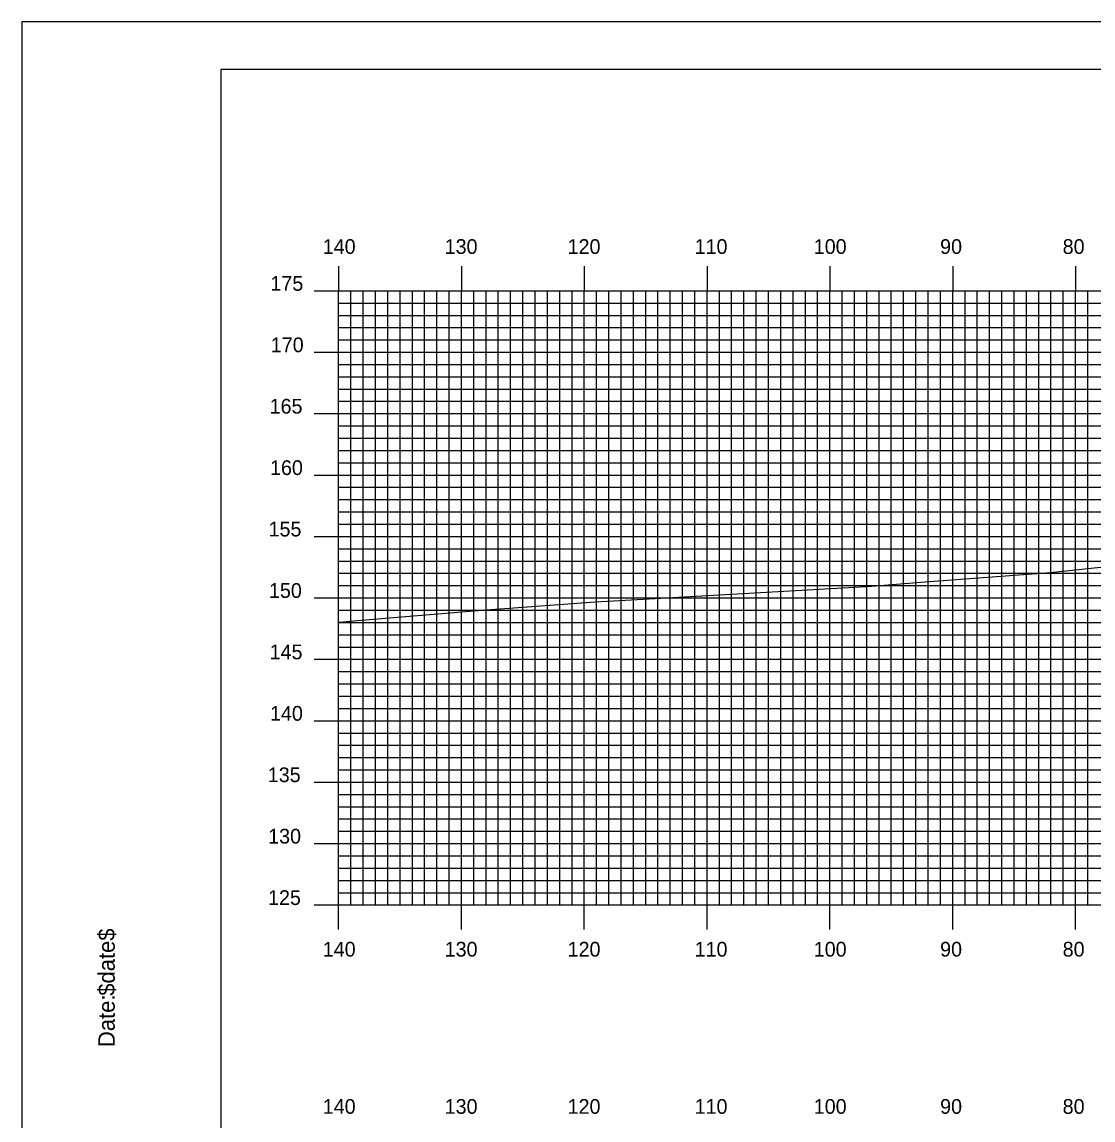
# Model space of a CAD drawing. Extents: x 1783041 to 1783384, y 442591 to 442811.
# Drawn here: x 1783040.7 to 1783127.9, y 442721.2 to 442810.5 of the extents above; entities that cross this region are included whole.
import ezdxf

# ---------------------------------------------------------------- set-up
doc = ezdxf.new("R2010")
doc.units = 0
for name, color, linetype in [('BORDER', 7, 'Continuous'), ('H_V ANNOTATION', 7, 'Continuous'), ('MAJOR', 7, 'Continuous'), ('MINOR', 7, 'Continuous'), ('PLOT BOUNDARY', 7, 'Continuous'), ('S_Roadway_Centerline', 7, 'Continuous')]:
    doc.layers.add(name, color=color, linetype=linetype)

msp = doc.modelspace()

# ---------------------------------------------------------------- linework, layer by layer
at = {"layer": 'BORDER'}
msp.add_lwpolyline([(1783056.86, 442596.665), (1783376.86, 442596.665), (1783376.86, 442806.665), (1783056.86, 442806.665)], close=True, dxfattribs=at)
at = {"layer": 'MAJOR'}
for p, q in [((1783066.46, 442790.669), (1783066.46, 442788.665)), ((1783076.46, 442790.669), (1783076.46, 442788.665)), ((1783086.46, 442790.669), (1783086.46, 442788.665)), ((1783096.46, 442790.669), (1783096.46, 442788.665)), ((1783106.46, 442790.669), (1783106.46, 442788.665)), ((1783116.46, 442790.669), (1783116.46, 442788.665)), ((1783126.46, 442790.669), (1783126.46, 442788.665)), ((1783064.456, 442788.665), (1783066.46, 442788.665)), ((1783066.46, 442788.665), (1783346.46, 442788.665)), ((1783066.46, 442738.665), (1783066.46, 442788.665)), ((1783066.46, 442738.665), (1783066.46, 442788.665)), ((1783066.46, 442788.665), (1783346.46, 442788.665)), ((1783076.46, 442738.665), (1783076.46, 442788.665)), ((1783086.46, 442738.665), (1783086.46, 442788.665)), ((1783096.46, 442738.665), (1783096.46, 442788.665)), ((1783106.46, 442738.665), (1783106.46, 442788.665)), ((1783116.46, 442738.665), (1783116.46, 442788.665)), ((1783126.46, 442738.665), (1783126.46, 442788.665)), ((1783064.456, 442783.665), (1783066.46, 442783.665)), ((1783066.46, 442783.665), (1783346.46, 442783.665)), ((1783064.456, 442778.665), (1783066.46, 442778.665)), ((1783066.46, 442778.665), (1783346.46, 442778.665)), ((1783064.456, 442773.665), (1783066.46, 442773.665)), ((1783066.46, 442773.665), (1783346.46, 442773.665)), ((1783064.456, 442768.665), (1783066.46, 442768.665)), ((1783066.46, 442768.665), (1783346.46, 442768.665)), ((1783064.456, 442763.665), (1783066.46, 442763.665)), ((1783066.46, 442763.665), (1783346.46, 442763.665)), ((1783064.456, 442758.665), (1783066.46, 442758.665)), ((1783066.46, 442758.665), (1783346.46, 442758.665)), ((1783064.456, 442753.665), (1783066.46, 442753.665)), ((1783066.46, 442753.665), (1783346.46, 442753.665)), ((1783064.456, 442748.665), (1783066.46, 442748.665)), ((1783066.46, 442748.665), (1783346.46, 442748.665)), ((1783064.456, 442743.665), (1783066.46, 442743.665)), ((1783066.46, 442743.665), (1783346.46, 442743.665)), ((1783064.456, 442738.665), (1783066.46, 442738.665)), ((1783066.46, 442738.665), (1783346.46, 442738.665)), ((1783066.46, 442738.665), (1783346.46, 442738.665)), ((1783066.46, 442736.661), (1783066.46, 442738.665)), ((1783076.46, 442736.661), (1783076.46, 442738.665)), ((1783086.46, 442736.661), (1783086.46, 442738.665)), ((1783096.46, 442736.661), (1783096.46, 442738.665)), ((1783106.46, 442736.661), (1783106.46, 442738.665)), ((1783116.46, 442736.661), (1783116.46, 442738.665)), ((1783126.46, 442736.661), (1783126.46, 442738.665))]:
    msp.add_line(p, q, dxfattribs=at)
at = {"layer": 'MINOR'}
for p, q in [((1783067.46, 442738.665), (1783067.46, 442788.665)), ((1783068.46, 442738.665), (1783068.46, 442788.665)), ((1783069.46, 442738.665), (1783069.46, 442788.665)), ((1783070.46, 442738.665), (1783070.46, 442788.665)), ((1783071.46, 442738.665), (1783071.46, 442788.665)), ((1783072.46, 442738.665), (1783072.46, 442788.665)), ((1783073.46, 442738.665), (1783073.46, 442788.665)), ((1783074.46, 442738.665), (1783074.46, 442788.665)), ((1783075.46, 442738.665), (1783075.46, 442788.665)), ((1783077.46, 442738.665), (1783077.46, 442788.665)), ((1783078.46, 442738.665), (1783078.46, 442788.665)), ((1783079.46, 442738.665), (1783079.46, 442788.665)), ((1783080.46, 442738.665), (1783080.46, 442788.665)), ((1783081.46, 442738.665), (1783081.46, 442788.665)), ((1783082.46, 442738.665), (1783082.46, 442788.665)), ((1783083.46, 442738.665), (1783083.46, 442788.665)), ((1783084.46, 442738.665), (1783084.46, 442788.665)), ((1783085.46, 442738.665), (1783085.46, 442788.665)), ((1783087.46, 442738.665), (1783087.46, 442788.665)), ((1783088.46, 442738.665), (1783088.46, 442788.665)), ((1783089.46, 442738.665), (1783089.46, 442788.665)), ((1783090.46, 442738.665), (1783090.46, 442788.665)), ((1783091.46, 442738.665), (1783091.46, 442788.665)), ((1783092.46, 442738.665), (1783092.46, 442788.665)), ((1783093.46, 442738.665), (1783093.46, 442788.665)), ((1783094.46, 442738.665), (1783094.46, 442788.665)), ((1783095.46, 442738.665), (1783095.46, 442788.665)), ((1783097.46, 442738.665), (1783097.46, 442788.665)), ((1783098.46, 442738.665), (1783098.46, 442788.665)), ((1783099.46, 442738.665), (1783099.46, 442788.665)), ((1783100.46, 442738.665), (1783100.46, 442788.665)), ((1783101.46, 442738.665), (1783101.46, 442788.665)), ((1783102.46, 442738.665), (1783102.46, 442788.665)), ((1783103.46, 442738.665), (1783103.46, 442788.665)), ((1783104.46, 442738.665), (1783104.46, 442788.665)), ((1783105.46, 442738.665), (1783105.46, 442788.665)), ((1783107.46, 442738.665), (1783107.46, 442788.665)), ((1783108.46, 442738.665), (1783108.46, 442788.665)), ((1783109.46, 442738.665), (1783109.46, 442788.665)), ((1783110.46, 442738.665), (1783110.46, 442788.665)), ((1783111.46, 442738.665), (1783111.46, 442788.665)), ((1783112.46, 442738.665), (1783112.46, 442788.665)), ((1783113.46, 442738.665), (1783113.46, 442788.665)), ((1783114.46, 442738.665), (1783114.46, 442788.665)), ((1783115.46, 442738.665), (1783115.46, 442788.665)), ((1783117.46, 442738.665), (1783117.46, 442788.665)), ((1783118.46, 442738.665), (1783118.46, 442788.665)), ((1783119.46, 442738.665), (1783119.46, 442788.665)), ((1783120.46, 442738.665), (1783120.46, 442788.665)), ((1783121.46, 442738.665), (1783121.46, 442788.665)), ((1783122.46, 442738.665), (1783122.46, 442788.665)), ((1783123.46, 442738.665), (1783123.46, 442788.665)), ((1783124.46, 442738.665), (1783124.46, 442788.665)), ((1783125.46, 442738.665), (1783125.46, 442788.665)), ((1783127.46, 442738.665), (1783127.46, 442788.665)), ((1783066.46, 442787.665), (1783346.46, 442787.665)), ((1783066.46, 442787.665), (1783068.464, 442787.665)), ((1783066.46, 442786.665), (1783346.46, 442786.665)), ((1783066.46, 442786.665), (1783068.464, 442786.665)), ((1783066.46, 442785.665), (1783346.46, 442785.665)), ((1783066.46, 442785.665), (1783068.464, 442785.665)), ((1783066.46, 442784.665), (1783346.46, 442784.665)), ((1783066.46, 442784.665), (1783068.464, 442784.665)), ((1783066.46, 442782.665), (1783346.46, 442782.665)), ((1783066.46, 442782.665), (1783068.464, 442782.665)), ((1783066.46, 442781.665), (1783346.46, 442781.665)), ((1783066.46, 442781.665), (1783068.464, 442781.665)), ((1783066.46, 442780.665), (1783346.46, 442780.665)), ((1783066.46, 442780.665), (1783068.464, 442780.665)), ((1783066.46, 442779.665), (1783346.46, 442779.665)), ((1783066.46, 442779.665), (1783068.464, 442779.665)), ((1783066.46, 442777.665), (1783346.46, 442777.665)), ((1783066.46, 442777.665), (1783068.464, 442777.665)), ((1783066.46, 442776.665), (1783346.46, 442776.665)), ((1783066.46, 442776.665), (1783068.464, 442776.665)), ((1783066.46, 442775.665), (1783346.46, 442775.665)), ((1783066.46, 442775.665), (1783068.464, 442775.665)), ((1783066.46, 442774.665), (1783346.46, 442774.665)), ((1783066.46, 442774.665), (1783068.464, 442774.665)), ((1783066.46, 442772.665), (1783346.46, 442772.665)), ((1783066.46, 442772.665), (1783068.464, 442772.665)), ((1783066.46, 442771.665), (1783346.46, 442771.665)), ((1783066.46, 442771.665), (1783068.464, 442771.665)), ((1783066.46, 442770.665), (1783346.46, 442770.665)), ((1783066.46, 442770.665), (1783068.464, 442770.665)), ((1783066.46, 442769.665), (1783346.46, 442769.665)), ((1783066.46, 442769.665), (1783068.464, 442769.665)), ((1783066.46, 442767.665), (1783346.46, 442767.665)), ((1783066.46, 442767.665), (1783068.464, 442767.665)), ((1783066.46, 442766.665), (1783346.46, 442766.665)), ((1783066.46, 442766.665), (1783068.464, 442766.665)), ((1783066.46, 442765.665), (1783346.46, 442765.665)), ((1783066.46, 442765.665), (1783068.464, 442765.665)), ((1783066.46, 442764.665), (1783346.46, 442764.665)), ((1783066.46, 442764.665), (1783068.464, 442764.665)), ((1783066.46, 442762.665), (1783346.46, 442762.665)), ((1783066.46, 442762.665), (1783068.464, 442762.665)), ((1783066.46, 442761.665), (1783346.46, 442761.665)), ((1783066.46, 442761.665), (1783068.464, 442761.665)), ((1783066.46, 442760.665), (1783346.46, 442760.665)), ((1783066.46, 442760.665), (1783068.464, 442760.665)), ((1783066.46, 442759.665), (1783346.46, 442759.665)), ((1783066.46, 442759.665), (1783068.464, 442759.665)), ((1783066.46, 442757.665), (1783346.46, 442757.665)), ((1783066.46, 442757.665), (1783068.464, 442757.665)), ((1783066.46, 442756.665), (1783346.46, 442756.665)), ((1783066.46, 442756.665), (1783068.464, 442756.665)), ((1783066.46, 442755.665), (1783346.46, 442755.665)), ((1783066.46, 442755.665), (1783068.464, 442755.665)), ((1783066.46, 442754.665), (1783346.46, 442754.665)), ((1783066.46, 442754.665), (1783068.464, 442754.665)), ((1783066.46, 442752.665), (1783346.46, 442752.665)), ((1783066.46, 442752.665), (1783068.464, 442752.665)), ((1783066.46, 442751.665), (1783346.46, 442751.665)), ((1783066.46, 442751.665), (1783068.464, 442751.665)), ((1783066.46, 442750.665), (1783346.46, 442750.665)), ((1783066.46, 442750.665), (1783068.464, 442750.665)), ((1783066.46, 442749.665), (1783346.46, 442749.665)), ((1783066.46, 442749.665), (1783068.464, 442749.665)), ((1783066.46, 442747.665), (1783346.46, 442747.665)), ((1783066.46, 442747.665), (1783068.464, 442747.665)), ((1783066.46, 442746.665), (1783346.46, 442746.665)), ((1783066.46, 442746.665), (1783068.464, 442746.665)), ((1783066.46, 442745.665), (1783346.46, 442745.665)), ((1783066.46, 442745.665), (1783068.464, 442745.665)), ((1783066.46, 442744.665), (1783346.46, 442744.665)), ((1783066.46, 442744.665), (1783068.464, 442744.665)), ((1783066.46, 442742.665), (1783346.46, 442742.665)), ((1783066.46, 442742.665), (1783068.464, 442742.665)), ((1783066.46, 442741.665), (1783346.46, 442741.665)), ((1783066.46, 442741.665), (1783068.464, 442741.665)), ((1783066.46, 442740.665), (1783346.46, 442740.665)), ((1783066.46, 442740.665), (1783068.464, 442740.665)), ((1783066.46, 442739.665), (1783346.46, 442739.665)), ((1783066.46, 442739.665), (1783068.464, 442739.665))]:
    msp.add_line(p, q, dxfattribs=at)
at = {"layer": 'PLOT BOUNDARY'}
msp.add_lwpolyline([(1783040.673, 442590.547), (1783380.673, 442590.547), (1783380.673, 442810.547), (1783040.673, 442810.547)], close=True, dxfattribs=at)
at = {"layer": 'S_Roadway_Centerline'}
msp.add_lwpolyline([(1783066.46, 442761.694), (1783066.492, 442761.697), (1783067.678, 442761.799), (1783078.115, 442762.665), (1783087.358, 442763.347), (1783091.732, 442763.584), (1783109.86, 442764.613), (1783114.215, 442764.969), (1783124.391, 442765.724), (1783132.852, 442766.623)], dxfattribs=at)

# ---------------------------------------------------------------- texts
at = {"layer": 'BORDER'}
for s, p in [('$date$', (1783048.23, 442731.275)), ('$date$', (1783048.23, 442731.275)), ('Date:', (1783048.23, 442727.099)), ('Date:', (1783048.23, 442727.099))]:
    msp.add_text(s, height=1.3392, rotation=90, dxfattribs=at).set_placement(p)
at = {"layer": 'H_V ANNOTATION'}
for s, p in [('140', (1783065.165, 442791.665)), ('130', (1783075.09, 442791.665)), ('120', (1783085.101, 442791.665)), ('110', (1783095.443, 442791.665)), ('100', (1783105.143, 442791.665)), ('90', (1783115.432, 442791.665)), ('80', (1783125.411, 442791.665)), ('175', (1783060.902, 442788.665)), ('170', (1783060.934, 442783.665)), ('165', (1783060.838, 442778.665)), ('160', (1783060.87, 442773.665)), ('155', (1783060.752, 442768.665)), ('150', (1783060.784, 442763.665)), ('145', (1783060.838, 442758.665)), ('140', (1783060.87, 442753.665)), ('135', (1783060.688, 442748.665)), ('130', (1783060.72, 442743.665)), ('125', (1783060.709, 442738.665)), ('140', (1783065.165, 442734.465)), ('130', (1783075.09, 442734.465)), ('120', (1783085.101, 442734.465)), ('110', (1783095.443, 442734.465)), ('100', (1783105.143, 442734.465)), ('90', (1783115.432, 442734.465)), ('80', (1783125.411, 442734.465)), ('140', (1783065.165, 442721.665)), ('130', (1783075.09, 442721.665)), ('120', (1783085.101, 442721.665)), ('110', (1783095.443, 442721.665)), ('100', (1783105.143, 442721.665)), ('90', (1783115.432, 442721.665)), ('80', (1783125.411, 442721.665))]:
    msp.add_text(s, height=1.2, dxfattribs=at).set_placement(p)
at = {"layer": 'MAJOR'}
msp.add_text('-', height=0.012, dxfattribs=at).set_placement((1783066.451, 442738.665))

doc.saveas('drawing.dxf')
